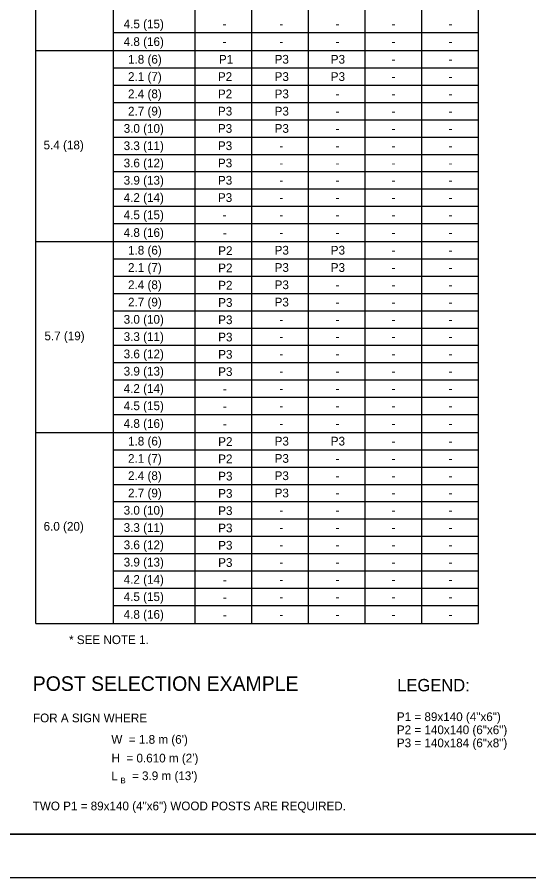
# Model space of a CAD drawing. Extents: x -1958 to 628, y -879 to 309.
# Drawn here: x -913 to -737.1, y -878.6 to -582.8 of the extents above; entities that cross this region are included whole.
import ezdxf

# ---------------------------------------------------------------- set-up
doc = ezdxf.new("R2010")
doc.units = 0
for name, color, linetype in [('1', 7, 'Continuous'), ('2', 7, 'Continuous'), ('3', 7, 'Continuous'), ('4', 7, 'Continuous'), ('PLT-BNDY', 7, 'Continuous')]:
    doc.layers.add(name, color=color, linetype=linetype)

msp = doc.modelspace()

# ---------------------------------------------------------------- linework, layer by layer
at = {"layer": '1'}
for p, q in [((-906.65, -791.15), (-906.65, -305.86)), ((-754.31, -791.15), (-754.31, -305.86)), ((-879.85, -791.15), (-879.85, -313.54)), ((-851.84, -791.15), (-851.84, -313.54)), ((-832.34, -791.15), (-832.34, -320.88)), ((-812.83, -791.15), (-812.83, -320.88)), ((-793.32, -791.15), (-793.32, -320.88)), ((-773.81, -791.15), (-773.81, -320.88)), ((-879.85, -588.11), (-754.31, -588.11)), ((-906.65, -594.32), (-754.31, -594.32)), ((-879.85, -600.26), (-754.31, -600.26)), ((-879.85, -606.2), (-754.31, -606.2)), ((-879.85, -612.14), (-754.31, -612.14)), ((-879.85, -618.08), (-754.31, -618.08)), ((-879.85, -624.02), (-754.31, -624.02)), ((-879.85, -629.96), (-754.31, -629.96)), ((-879.85, -635.9), (-754.31, -635.9)), ((-879.85, -641.84), (-754.31, -641.84)), ((-879.85, -647.78), (-754.31, -647.78)), ((-879.85, -653.72), (-754.31, -653.72)), ((-906.65, -659.93), (-754.31, -659.93)), ((-879.85, -665.87), (-754.31, -665.87)), ((-879.85, -671.81), (-754.31, -671.81)), ((-879.85, -677.75), (-754.31, -677.75)), ((-879.85, -683.69), (-754.31, -683.69)), ((-879.85, -689.63), (-754.31, -689.63)), ((-879.85, -695.57), (-754.31, -695.57)), ((-879.85, -701.51), (-754.31, -701.51)), ((-879.85, -707.45), (-754.31, -707.45)), ((-879.85, -713.39), (-754.31, -713.39)), ((-879.85, -719.33), (-754.31, -719.33)), ((-906.65, -725.54), (-754.31, -725.54)), ((-777.86, -725.54), (-754.31, -725.54)), ((-879.85, -731.48), (-754.31, -731.48)), ((-777.86, -731.48), (-754.31, -731.48)), ((-879.85, -737.42), (-754.31, -737.42)), ((-777.86, -737.42), (-754.31, -737.42)), ((-879.85, -743.36), (-754.31, -743.36)), ((-777.86, -743.36), (-754.31, -743.36)), ((-879.85, -749.3), (-754.31, -749.3)), ((-879.85, -755.24), (-754.31, -755.24)), ((-777.86, -755.24), (-754.31, -755.24)), ((-879.85, -761.18), (-754.31, -761.18)), ((-777.86, -761.18), (-754.31, -761.18)), ((-879.85, -767.12), (-754.31, -767.12)), ((-777.86, -767.12), (-754.31, -767.12)), ((-879.85, -773.06), (-754.31, -773.06)), ((-777.86, -773.06), (-754.31, -773.06)), ((-879.85, -779), (-754.31, -779)), ((-777.86, -779), (-754.31, -779)), ((-879.85, -784.94), (-754.31, -784.94)), ((-777.86, -784.94), (-754.31, -784.94)), ((-906.65, -791.15), (-754.31, -791.15)), ((-291.39, -863.56), (-1077.39, -863.56)), ((-1077.39, -863.56), (-491.39, -863.56))]:
    msp.add_line(p, q, dxfattribs=at)
at = {"layer": 'PLT-BNDY'}
msp.add_lwpolyline([(-1117.39, -284.56), (-276.39, -284.56), (-276.39, -878.56), (-1117.39, -878.56)], close=True, dxfattribs=at)

# ---------------------------------------------------------------- texts
at = {"layer": '1'}
for s, height, p in [('4.5 (15)', 3, (-876.4, -586.64)), ('-', 3, (-842.36, -586.64)), ('-', 3, (-822.86, -586.64)), ('-', 3, (-803.55, -586.64)), ('-', 3, (-784.29, -586.64)), ('-', 3, (-764.69, -586.64)), ('4.8 (16)', 3, (-876.4, -592.72)), ('-', 3, (-842.36, -592.72)), ('-', 3, (-822.86, -592.72)), ('-', 3, (-803.55, -592.72)), ('-', 3, (-784.29, -592.72)), ('-', 3, (-764.69, -592.72)), ('1.8 (6)', 3, (-874.9, -598.79)), ('P1', 3, (-843.64, -598.79)), ('P3', 3, (-824.48, -598.79)), ('P3', 3, (-805.17, -598.79)), ('-', 3, (-784.29, -598.79)), ('-', 3, (-764.69, -598.79)), ('2.1 (7)', 3, (-874.9, -604.73)), ('P2', 3, (-843.98, -604.73)), ('P3', 3, (-824.48, -604.73)), ('P3', 3, (-805.17, -604.73)), ('-', 3, (-784.29, -604.73)), ('-', 3, (-764.69, -604.73)), ('2.4 (8)', 3, (-874.9, -610.67)), ('P2', 3, (-843.98, -610.67)), ('P3', 3, (-824.48, -610.67)), ('-', 3, (-803.55, -610.67)), ('-', 3, (-784.29, -610.67)), ('-', 3, (-764.69, -610.67)), ('2.7 (9)', 3, (-874.9, -616.61)), ('P3', 3, (-843.98, -616.61)), ('P3', 3, (-824.48, -616.61)), ('-', 3, (-803.55, -616.61)), ('-', 3, (-784.29, -616.61)), ('-', 3, (-764.69, -616.61)), ('3.0 (10)', 3, (-876.4, -622.55)), ('P3', 3, (-843.98, -622.55)), ('P3', 3, (-824.48, -622.55)), ('-', 3, (-803.55, -622.55)), ('-', 3, (-784.29, -622.55)), ('-', 3, (-764.69, -622.55)), ('5.4 (18)', 3, (-903.94, -628.24)), ('3.3 (11)', 3, (-876.4, -628.49)), ('P3', 3, (-843.98, -628.49)), ('-', 3, (-822.86, -628.49)), ('-', 3, (-803.55, -628.49)), ('-', 3, (-784.29, -628.49)), ('-', 3, (-764.69, -628.49)), ('3.6 (12)', 3, (-876.4, -634.43)), ('P3', 3, (-843.98, -634.43)), ('-', 3, (-822.86, -634.43)), ('-', 3, (-803.55, -634.43)), ('-', 3, (-784.29, -634.43)), ('-', 3, (-764.69, -634.43)), ('3.9 (13)', 3, (-876.4, -640.37)), ('P3', 3, (-843.98, -640.37)), ('-', 3, (-822.86, -640.37)), ('-', 3, (-803.55, -640.37)), ('-', 3, (-784.29, -640.37)), ('-', 3, (-764.69, -640.37)), ('4.2 (14)', 3, (-876.4, -646.31)), ('P3', 3, (-843.98, -646.31)), ('-', 3, (-822.86, -646.31)), ('-', 3, (-803.55, -646.31)), ('-', 3, (-784.29, -646.31)), ('-', 3, (-764.69, -646.31)), ('4.5 (15)', 3, (-876.4, -652.25)), ('-', 3, (-842.36, -652.25)), ('-', 3, (-822.86, -652.25)), ('-', 3, (-803.55, -652.25)), ('-', 3, (-784.29, -652.25)), ('-', 3, (-764.69, -652.25)), ('4.8 (16)', 3, (-876.4, -658.33)), ('-', 3, (-842.27, -658.46)), ('-', 3, (-822.86, -658.33)), ('-', 3, (-803.55, -658.33)), ('-', 3, (-784.29, -658.33)), ('-', 3, (-764.69, -658.33)), ('1.8 (6)', 3, (-874.9, -664.4)), ('P2', 3, (-843.89, -664.54)), ('P3', 3, (-824.48, -664.4)), ('P3', 3, (-805.17, -664.4)), ('-', 3, (-784.29, -664.4)), ('-', 3, (-764.69, -664.4)), ('2.1 (7)', 3, (-874.9, -670.34)), ('P2', 3, (-843.89, -670.48)), ('P3', 3, (-824.48, -670.34)), ('P3', 3, (-805.17, -670.34)), ('-', 3, (-784.29, -670.34)), ('-', 3, (-764.69, -670.34)), ('2.4 (8)', 3, (-874.9, -676.28)), ('P2', 3, (-843.89, -676.42)), ('P3', 3, (-824.48, -676.28)), ('-', 3, (-803.55, -676.28)), ('-', 3, (-784.29, -676.28)), ('-', 3, (-764.69, -676.28)), ('2.7 (9)', 3, (-874.9, -682.22)), ('P3', 3, (-843.89, -682.36)), ('P3', 3, (-824.48, -682.22)), ('-', 3, (-803.55, -682.22)), ('-', 3, (-784.29, -682.22)), ('-', 3, (-764.69, -682.22)), ('3.0 (10)', 3, (-876.4, -688.16)), ('P3', 3, (-843.89, -688.3)), ('-', 3, (-822.86, -688.16)), ('-', 3, (-803.55, -688.16)), ('-', 3, (-784.29, -688.16)), ('-', 3, (-764.69, -688.16)), ('5.7 (19)', 3, (-903.65, -693.85)), ('3.3 (11)', 3, (-876.4, -694.1)), ('P3', 3, (-843.89, -694.24)), ('-', 3, (-822.86, -694.1)), ('-', 3, (-803.55, -694.1)), ('-', 3, (-784.29, -694.1)), ('-', 3, (-764.69, -694.1)), ('3.6 (12)', 3, (-876.4, -700.04)), ('P3', 3, (-843.89, -700.18)), ('-', 3, (-822.86, -700.04)), ('-', 3, (-803.55, -700.04)), ('-', 3, (-784.29, -700.04)), ('-', 3, (-764.69, -700.04)), ('3.9 (13)', 3, (-876.4, -705.98)), ('P3', 3, (-843.89, -706.12)), ('-', 3, (-822.86, -705.98)), ('-', 3, (-803.55, -705.98)), ('-', 3, (-784.29, -705.98)), ('-', 3, (-764.69, -705.98)), ('4.2 (14)', 3, (-876.4, -711.92)), ('-', 3, (-842.27, -712.06)), ('-', 3, (-822.86, -711.92)), ('-', 3, (-803.55, -711.92)), ('-', 3, (-784.29, -711.92)), ('-', 3, (-764.69, -711.92)), ('4.5 (15)', 3, (-876.4, -717.86)), ('-', 3, (-842.27, -718)), ('-', 3, (-822.86, -717.86)), ('-', 3, (-803.55, -717.86)), ('-', 3, (-784.29, -717.86)), ('-', 3, (-764.69, -717.86)), ('4.8 (16)', 3, (-876.4, -723.94)), ('-', 3, (-842.27, -724.07)), ('-', 3, (-822.86, -723.94)), ('-', 3, (-803.55, -723.94)), ('-', 3, (-784.29, -723.94)), ('-', 3, (-764.69, -723.94)), ('1.8 (6)', 3, (-874.9, -730.01)), ('P2', 3, (-843.89, -730.15)), ('P3', 3, (-824.48, -730.01)), ('P3', 3, (-805.17, -730.01)), ('-', 3, (-784.29, -730.01)), ('-', 3, (-764.69, -730.01)), ('2.1 (7)', 3, (-874.9, -735.95)), ('P2', 3, (-843.89, -736.09)), ('P3', 3, (-824.48, -735.95)), ('-', 3, (-803.55, -735.95)), ('-', 3, (-784.29, -735.95)), ('-', 3, (-764.69, -735.95)), ('2.4 (8)', 3, (-874.9, -741.89)), ('P3', 3, (-843.89, -742.03)), ('P3', 3, (-824.48, -741.89)), ('-', 3, (-803.55, -741.89)), ('-', 3, (-784.29, -741.89)), ('-', 3, (-764.69, -741.89)), ('2.7 (9)', 3, (-874.9, -747.83)), ('P3', 3, (-843.89, -747.97)), ('P3', 3, (-824.48, -747.83)), ('-', 3, (-803.55, -747.83)), ('-', 3, (-784.29, -747.83)), ('-', 3, (-764.69, -747.83)), ('3.0 (10)', 3, (-876.4, -753.77)), ('P3', 3, (-843.89, -753.91)), ('-', 3, (-822.86, -753.77)), ('-', 3, (-803.55, -753.77)), ('-', 3, (-784.29, -753.77)), ('-', 3, (-764.69, -753.77)), ('6.0 (20)', 3, (-903.94, -759.28)), ('3.3 (11)', 3, (-876.4, -759.71)), ('P3', 3, (-843.89, -759.85)), ('-', 3, (-822.86, -759.71)), ('-', 3, (-803.55, -759.71)), ('-', 3, (-784.29, -759.71)), ('-', 3, (-764.69, -759.71)), ('3.6 (12)', 3, (-876.4, -765.65)), ('P3', 3, (-843.89, -765.79)), ('-', 3, (-822.86, -765.65)), ('-', 3, (-803.55, -765.65)), ('-', 3, (-784.29, -765.65)), ('-', 3, (-764.69, -765.65)), ('3.9 (13)', 3, (-876.4, -771.59)), ('P3', 3, (-843.89, -771.73)), ('-', 3, (-822.86, -771.59)), ('-', 3, (-803.55, -771.59)), ('-', 3, (-784.29, -771.59)), ('-', 3, (-764.69, -771.59)), ('4.2 (14)', 3, (-876.4, -777.53)), ('-', 3, (-842.27, -777.67)), ('-', 3, (-822.86, -777.53)), ('-', 3, (-803.55, -777.53)), ('-', 3, (-784.29, -777.53)), ('-', 3, (-764.69, -777.53)), ('4.5 (15)', 3, (-876.4, -783.47)), ('-', 3, (-842.27, -783.61)), ('-', 3, (-822.86, -783.47)), ('-', 3, (-803.55, -783.47)), ('-', 3, (-784.29, -783.47)), ('-', 3, (-764.69, -783.47)), ('4.8 (16)', 3, (-876.4, -789.55)), ('-', 3, (-842.27, -789.68)), ('-', 3, (-822.86, -789.55)), ('-', 3, (-803.55, -789.55)), ('-', 3, (-784.29, -789.55)), ('-', 3, (-764.69, -789.55)), ('FOR A SIGN WHERE ', 3, (-907.58, -825.13)), ("W  = 1.8 m (6')", 3, (-880.63, -832.51)), ("H  = 0.610 m (2')", 3, (-880.58, -838.93)), ('L', 3, (-880.63, -845.08)), (" = 3.9 m (13')", 3, (-874.65, -845)), ('B', 2, (-877.49, -846.14)), ('TWO P1 = 89x140 (4"x6") WOOD POSTS ARE REQUIRED.', 3, (-907.69, -855.38))]:
    msp.add_text(s, height=height, dxfattribs=at).set_placement(p)
at = {"layer": '2'}
msp.add_text('POST SELECTION EXAMPLE', height=5, dxfattribs=at).set_placement((-907.67, -814.33))
at = {"layer": '3'}
for s, height, p in [('* SEE NOTE 1.', 3, (-895.18, -798.25)), ('LEGEND:', 4.25, (-782.32, -814.49))]:
    msp.add_text(s, height=height, dxfattribs=at).set_placement(p)
at = {"layer": '4'}
for s, p in [('P1 = 89x140 (4"x6")', (-782.44, -824.71)), ('P2 = 140x140 (6"x6")', (-782.44, -829.21)), ('P3 = 140x184 (6"x8")', (-782.44, -833.71))]:
    msp.add_text(s, height=3, dxfattribs=at).set_placement(p)

doc.saveas('drawing.dxf')
